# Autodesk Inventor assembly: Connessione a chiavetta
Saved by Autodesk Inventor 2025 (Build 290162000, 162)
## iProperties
ClientObjectVersion: 1
Created: 2026-05
Part Number: Connessione a chiavetta
Document SubType Name: Assembly
Designer: Ryzen5700u
Author: Ryzen5700u
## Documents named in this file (1)
- C:\Users\Ryzen5700u\Desktop\riduttore pompa\riduttore2\Design Accelerator\Connessione a chiavetta3.iam
